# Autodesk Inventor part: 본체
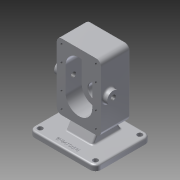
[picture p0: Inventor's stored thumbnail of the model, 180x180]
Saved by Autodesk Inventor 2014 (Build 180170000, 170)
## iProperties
Created: 2020-04
Part Number: 본체
Material: 알루미늄 6061
Document SubType Name: Modeling
Designer: kh
Density: 2.71 g/cm^3
Appearance: 알루미늄 - 평지
Mass: 1476.44 g
Surface Area: 819.925 cm^2
Volume: 544.812 cm^3
Author: kh
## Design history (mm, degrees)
sketch "스케치1"
  geometry: L1 (-50, -60)-(50, -60); L2 (50, -60)-(50, 60); L3 (50, 60)-(-50, 60); L4 (-50, 60)-(-50, -60); L5 (-50, -60)-(50, 60); L6 (50, -60)-(-50, 60); 1 further point
  constraints: 12 end point, 2 midpoint, 2 parallel, 1 horizontal, 1 perpendicular
  dimensions: "d0" = 100 distance of L2.end L3.end; "d1" = 120 distance of L3.end L1.start
extrude "돌출1" new body sketch "스케치1" distance "d2" = 10; taper "d3" = 0 deg
node "작업 평면3"
sketch "스케치2"
  geometry: L1 (20, 150)-(100, 150); L2 (100, 150)-(100, 30); L3 (100, 30)-(20, 30); L4 (20, 30)-(20, 150); L5 (60, 0)-(60, 4.946); L6 (120, 0)-(0, 0) reference
  constraints: 10 end point, 3 parallel, 1 horizontal, 1 perpendicular, 1 other
  dimensions: "d7" = 150 distance between parallel lines of L6 L1; "d8" = 120 distance between parallel lines of L3 L1; "d9" = 80 distance of L1.start L1.end
extrude "돌출2" join sketch "스케치2" distance "d10" = 53; taper "d11" = 0 deg
fillet "모깎기1" dims "d12" = 10
sketch "스케치3"
  geometry: L1 (-60, 112)-(-60, 68); L2 (-84, 112)-(-84, 68); L3 (-36, 68)-(-36, 112); L4 (-110, 0)-(-10, 0) reference; A1 r 24 centre (-60, 112) between (-36, 112) and (-84, 112); A2 r 24 centre (-60, 68) between (-84, 68) and (-36, 68); 3 further points
  constraints: 8 end point, 4 point on circle, 4 tangent, 2 centre point, 2 midpoint, 1 parallel, 1 vertical, 1 vertical alignment
  dimensions: "d13" = 24 radius of A1; "d14" = 90 distance from line of L4 point (-60, 90); "d15" = 44 distance of L1.end L1.start
extrude "돌출3" cut sketch "스케치3" distance "d16" = 29; taper "d17" = 0 deg
hole "구멍2" diameter "d29" = 25; stored, may be unused: countersink angle "d33" = 90 deg, drill point angle "d35" = 0 deg; dims "d27" = 10, "d28" = 10, "d30" = 6, "d31" = 4, "d32" = 2, "d34" = 15
hole "구멍5" diameter "d59" = 25; stored, may be unused: countersink angle "d63" = 90 deg, drill point angle "d65" = 0 deg; dims "d57" = 10, "d58" = 10, "d60" = 6, "d61" = 4, "d62" = 2, "d64" = 15
fillet "모깎기2" dims "d66" = 9
sketch "스케치6"
  geometry: C1 r 12.5 at (60, 112) reference; C2 r 19 at (60, 112); 1 further point
  constraints: 1 centre point, 1 coincident
  dimensions: "d67" = 38 diameter of C2
extrude "돌출4" join sketch "스케치6" distance "d68" = 17; taper "d69" = 0 deg
hole "구멍6" diameter "d72" = 17; stored, may be unused: countersink angle "d76" = 90 deg, drill point angle "d78" = 0 deg; dims "d70" = 10, "d71" = 10, "d73" = 6, "d74" = 4, "d75" = 2, "d77" = 15
hole "구멍7" diameter "d81" = 28; stored, may be unused: countersink angle "d85" = 90 deg, drill point angle "d87" = 0 deg; dims "d79" = 10, "d80" = 10, "d82" = 6, "d83" = 4, "d84" = 2, "d86" = 7.3
chamfer "모따기2" distance "d88" = 0.7; stored, may be unused: second distance "d89" = 2, angle "d90" = 30 deg
sketch "스케치7"
  geometry: L1 (33, 30)-(-20, 30) reference; L2 (40, 10)-(-40, 10) reference; L3 (-20, 10)-(-8.453, 30); L4 (21.453, 30)-(33, 10); L5 (50, 10)-(50, 0) reference; L6 (-8.453, 30)-(21.453, 30); L7 (-20, 10)-(33, 10); 1 further point
  constraints: 8 end point, 4 point on line, 2 collinear
  dimensions: "d91" = 17 distance from line of L5 L4.end; "d92" = 53 distance of L4.end L3.start; "d93" = 60 deg angle of L2 L3; "d94" = 60 deg angle of L2 L4
extrude "돌출5" join sketch "스케치7" stored distance "d95" = 48; taper "d96" = 0 deg
sketch "스케치8"
  geometry: L1 (40, 60)-(-40, 60) reference; L2 (50, -50)-(50, 50) reference; L3 (-40, -60)-(40, -60) reference; L4 (-50, 50)-(-50, -50) reference; A1 r 10 centre (-40, 50) between (-40, 60) and (-50, 50) reference; A2 r 10 centre (40, 50) between (50, 50) and (40, 60) reference; A3 r 10 centre (40, -50) between (40, -60) and (50, -50) reference; A4 r 10 centre (-40, -50) between (-50, -50) and (-40, -60) reference; 1 further point
hole "구멍8" sketch "스케치8" at (-40, 50), (40, 50), (-40, -50), (40, -50) diameter "d97" = 9; stored, may be unused: countersink angle "d101" = 90 deg, drill point angle "d103" = 0 deg; dims "d98" = 6, "d99" = 4, "d100" = 2, "d102" = 7.3
sketch "스케치9"
  geometry: L1 (-84, 68)-(-84, 112) reference; L2 (-36, 112)-(-36, 68) reference; L3 (-100, 141)-(-100, 39) reference; L4 (-91, 30)-(-29, 30) reference; L5 (-20, 39)-(-20, 141) reference; L6 (-29, 150)-(-91, 150) reference; A1 r 24 centre (-60, 68) between (-84, 68) and (-36, 68) reference; A2 r 24 centre (-60, 112) between (-36, 112) and (-84, 112) reference; A3 r 9 centre (-91, 141) between (-91, 150) and (-100, 141) reference; A4 r 9 centre (-91, 39) between (-100, 39) and (-91, 30) reference; A5 r 9 centre (-29, 39) between (-29, 30) and (-20, 39) reference; A6 r 9 centre (-29, 141) between (-20, 141) and (-29, 150) reference; 5 further points
  constraints: 4 vertical alignment
  dimensions: "d104" = 29 distance of point (-29, 112) A6.centre; "d105" = 29 distance of point (-91, 112) A3.centre; "d106" = 44 distance of point (-29, 68) point (-29, 112); "d107" = 44 distance of point (-91, 112) point (-91, 68)
hole "구멍9" sketch "스케치9" at (-91, 112), (-29, 112), (-29, 68), (-91, 68), (-91, 39), (-29, 39), (-29, 141), (-91, 141) diameter "d108" = 4.459; stored, may be unused: countersink angle "d112" = 90 deg, drill point angle "d114" = 118 deg; dims "d109" = 10, "d110" = 4, "d111" = 2, "d113" = 12
sketch "스케치10"
  geometry: L1 (-53, 0)-(-53, 102) reference; L2 (-73, -39)-(7, -39) reference; C1 r 11 at (-39, 51); 1 further point
  constraints: 1 centre point
  dimensions: "d115" = 22 diameter of C1; "d116" = 14 distance from line of L1 C1.centre; "d117" = 90 distance from line of L2 C1.centre
extrude "돌출6" join sketch "스케치10" distance "d118" = 8; taper "d119" = 0 deg
fillet "모깎기4" dims "d121" = 3
hole "구멍10" diameter "d124" = 8.917; stored, may be unused: countersink angle "d128" = 90 deg, drill point angle "d130" = 118 deg; dims "d125" = 10, "d126" = 4, "d127" = 2, "d129" = 12, "d145" = 10, "d146" = 10
sketch "스케치11"
  geometry: L1 (-50, 50)-(-50, -50) reference; L2 (40, 60)-(-40, 60) reference; L3 (-31.634, 25.099)-(-31.634, -25.099); L4 (-31.634, -25.099)-(-48.366, -25.099); L5 (-48.366, -25.099)-(-48.366, 25.099); L6 (-48.366, 25.099)-(-31.634, 25.099); L7 (-48.366, 25.099)-(-31.634, -25.099); L8 (-31.634, 25.099)-(-48.366, -25.099); 3 further points
  constraints: 4 end point, 1 coincident, 1 midpoint, 2 other
  dimensions: "d131" = 10 distance from line of L1 point (-40, 0); "d132" = 60 distance from line of L2 point (-40, 0)
feature "엠보싱1" sketch "스케치11" dims "d0" = 100, "d1" = 120, "d133" = 0.5, "d134" = 0
fillet "모깎기5" dims "d135" = 3
fillet "모깎기6" dims "d136" = 3
fillet "모깎기7" dims "d137" = 3
fillet "모깎기8" dims "d138" = 0.5
chamfer "모따기3" distance "d139" = 1; stored, may be unused: second distance "d140" = 2, angle "d141" = 30 deg
fillet "모깎기9" dims "d142" = 3
fillet "모깎기11" dims "d144" = 3
node "솔리드1"
mirror "대칭1"
node "투영된 루프1"
node "투영된 루프2"
other parameters: "d6" = -17
